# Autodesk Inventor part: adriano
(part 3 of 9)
sketch "スケッチ93"
  geometry: L1 (3.5, 3.5)-(0.5, 3.5) reference; L2 (0.5, 3.5)-(0.5, 0.5) reference; L3 (0.5, 0.5)-(3.5, 0.5) reference; L4 (3.5, 0.5)-(3.5, 3.5) reference; L5 (1.5, 2.5)-(2.5, 2.5); L6 (2.5, 2.5)-(2.5, 1.5); L7 (2.5, 1.5)-(1.5, 1.5); L8 (1.5, 1.5)-(1.5, 2.5); 1 further point
  constraints: 8 end point, 2 parallel, 1 horizontal, 1 perpendicular
  dimensions: "d958" = 1 distance between parallel lines of L1 L5; "d959" = 1 distance between parallel lines of L3 L7; "d960" = 1 distance between parallel lines of L2 L8; "d961" = 1 distance between parallel lines of L4 L6
extrude "押し出し90" join sketch "スケッチ93" distance "d962" = 3; taper "d963" = 0 deg
sketch "スケッチ94"
  geometry: L1 (0, 3)-(1, 3) reference; C1 r 0.8 at (0.5, 3); 1 further point
  constraints: 1 centre point, 1 midpoint
  dimensions: "d964" = 1.6 diameter of C1
extrude "押し出し91" join sketch "スケッチ94" distance "d967" = 0.8; taper "d968" = 0 deg
sketch "スケッチ95"
  geometry: L1 (20, 22)-(20, 26) reference; L2 (22, 0)-(22, 22) reference; L3 (22, 22)-(20, 22) reference; L4 (22, 20.8)-(23.6, 22); L5 (23.6, 22)-(20.4, 22); L6 (20.4, 22)-(22, 20.8); L7 (20, 22)-(24, 22) reference; L8 (24, 22)-(24, 34) reference; 1 further point
  constraints: 6 end point, 1 collinear, 1 point on line
  dimensions: "d969" = 0 distance between parallel lines of L7 L5; "d970" = 0.4 distance from line of L5.end L1; "d971" = 0.4 distance from line of L8 L4.end; "d972" = 1.2 distance from line of L5 L4.start
extrude "押し出し92" join sketch "スケッチ95" distance "d973" = 1; taper "d974" = 0 deg
sketch "スケッチ96"
  geometry: L1 (22, 0)-(22, 20.8) reference; L2 (22, 20.8)-(23.6, 22) reference; L3 (22, 20.8)-(20.4, 22); L4 (20.4, 22)-(23.6, 22); L5 (23.6, 22)-(22, 20.8); 2 further points
  constraints: 6 end point, 1 perpendicular
  dimensions: "d975" = 0.4 distance of point (20, 22) L3.end; "d976" = 0 distance between parallel lines of L2 L5
extrude "押し出し93" join sketch "スケッチ96" distance "d977" = 1; taper "d978" = 0 deg
sketch "スケッチ97"
  geometry: L1 (24, 34)-(20, 34) reference; L2 (20, 34)-(20, 22) reference; L3 (21.5, 31)-(22.5, 31); L4 (22.5, 31)-(22.5, 29.5); L5 (22.5, 29.5)-(21.5, 29.5); L6 (21.5, 29.5)-(21.5, 31); 1 further point
  constraints: 8 end point, 2 parallel, 1 horizontal, 1 perpendicular
  dimensions: "d979" = 1 distance of L3.start L3.end; "d981" = 1.5 distance of L3.end L4.end; "d982" = 1.5 distance between parallel lines of L6 L2; "d983" = 3 distance between parallel lines of L1 L3
extrude "押し出し94" cut sketch "スケッチ97" distance "d984" = 2; taper "d985" = 0 deg
sketch "スケッチ98"
  geometry: L1 (-19.412, -18.314)-(-19.412, 9.686) reference; L2 (7.588, -18.314)-(-19.412, -18.314) reference; L3 (-16.412, -4.314)-(-2.412, -4.314); L4 (-2.412, -4.314)-(-2.412, -14.314); L5 (-2.412, -14.314)-(-16.412, -14.314); L6 (-16.412, -14.314)-(-16.412, -4.314); 1 further point
  constraints: 8 end point, 2 parallel, 1 horizontal, 1 perpendicular
  dimensions: "d986" = 3 distance between parallel lines of L6 L1; "d987" = 4 distance between parallel lines of L2 L5; "d988" = 14 distance of L4.end L5.end; "d989" = 10 distance of L5.end L3.start
extrude "押し出し95" cut sketch "スケッチ98" distance "d990" = 0.5; taper "d991" = 0 deg
sketch "スケッチ99"
  geometry: L1 (-16.412, -4.314)-(-2.412, -4.314) reference; L2 (-16.412, -14.314)-(-16.412, -4.314) reference; L3 (-2.412, -14.314)-(-16.412, -14.314) reference; L4 (-2.412, -4.314)-(-2.412, -14.314) reference; L5 (-15.412, -5.314)-(-3.412, -5.314); L6 (-3.412, -5.314)-(-3.412, -13.314); L7 (-3.412, -13.314)-(-15.412, -13.314); L8 (-15.412, -13.314)-(-15.412, -5.314); 1 further point
  constraints: 8 end point, 2 parallel, 1 horizontal, 1 perpendicular
  dimensions: "d992" = 1 distance between parallel lines of L1 L5; "d993" = 1 distance between parallel lines of L2 L8; "d994" = 1 distance between parallel lines of L4 L6; "d995" = 1 distance between parallel lines of L3 L7
extrude "押し出し96" cut sketch "スケッチ99" distance "d996" = 1; taper "d997" = 0 deg
sketch "スケッチ100"
  geometry: L1 (-15.412, -5.314)-(-3.412, -5.314) reference; L2 (-15.412, -13.314)-(-15.412, -5.314) reference; L3 (-9.912, -8.814)-(-8.912, -8.814); L4 (-8.912, -8.814)-(-8.912, -9.814); L5 (-8.912, -9.814)-(-9.912, -9.814); L6 (-9.912, -9.814)-(-9.912, -8.814); 1 further point
  constraints: 8 end point, 2 parallel, 1 horizontal, 1 perpendicular
  dimensions: "d998" = 1 distance of L3.start L3.end; "d1000" = 1 distance of L3.end L4.end; "d1001" = 3.5 distance between parallel lines of L1 L3; "d1002" = 5.5 distance between parallel lines of L2 L6
extrude "押し出し97" join sketch "スケッチ100" distance "d1003" = 1; taper "d1004" = 0 deg
sketch "スケッチ101"
  geometry: L1 (0, 4)-(4, 4) reference; L2 (0, 0)-(0, 4) reference; L3 (0, 0)-(4, 0) reference; L4 (4, 4)-(4, 0) reference; L5 (-0.5, 4.5)-(4.5, 4.5); L6 (4.5, 4.5)-(4.5, -0.5); L7 (4.5, -0.5)-(-0.5, -0.5); L8 (-0.5, -0.5)-(-0.5, 4.5); 1 further point
  constraints: 8 end point, 2 parallel, 1 horizontal, 1 perpendicular
  dimensions: "d1005" = 0.5 distance between parallel lines of L8 L2; "d1006" = 0.5 distance between parallel lines of L5 L1; "d1007" = 0.5 distance between parallel lines of L7 L3; "d1008" = 0.5 distance between parallel lines of L6 L4
extrude "押し出し98" join sketch "スケッチ101" distance "d1009" = 1; taper "d1010" = 0 deg
sketch "スケッチ102"
  geometry: L1 (82.588, 32.686)-(82.588, 25.686) reference; L2 (113.588, 30.686)-(113.588, 11.686) reference; L3 (83.588, 25.686)-(83.588, -26.314); L4 (83.588, -26.314)-(58.588, -26.314); L5 (58.588, -26.314)-(58.588, -13.314); L6 (58.588, -13.314)-(27.588, -13.314); L7 (27.588, -13.314)-(27.588, 12.686); L8 (27.588, 12.686)-(58.588, 12.686); L9 (58.588, 12.686)-(58.588, 25.686); L10 (58.588, 25.686)-(83.588, 25.686); L11 (58.588, 25.686)-(58.588, 43.005) reference; 1 further point
  constraints: 16 end point, 6 parallel, 2 perpendicular
  dimensions: "d1012" = 52 distance of L3.start L3.end; "d1015" = 0 distance between parallel lines of L5 L9; "d1017" = 56 distance between parallel lines of L3 L7; "d1018" = 13 distance between parallel lines of L8 L10; "d1019" = 13 distance between parallel lines of L4 L6; "d1020" = 0 distance from line of L1.end L10; "d1021" = 1 distance between parallel lines of L3 L1; "d1024" = 0 distance between parallel lines of L9 L11
extrude "hotel" join sketch "スケッチ102" distance "d1022" = 34; taper "d1023" = 0 deg
sketch "スケッチ103"
  geometry: L1 (83.588, -26.314)-(83.588, 25.686) reference; L2 (83.588, 25.686)-(58.588, 25.686) reference; L3 (58.588, 25.686)-(58.588, 12.686) reference; L4 (58.588, 12.686)-(27.588, 12.686) reference; L5 (27.588, 12.686)-(27.588, -13.314) reference; L6 (27.588, -13.314)-(58.588, -13.314) reference; L7 (58.588, -13.314)-(58.588, -26.314) reference; L8 (58.588, -26.314)-(83.588, -26.314) reference; L9 (29.588, 10.686)-(29.588, -11.314); L10 (29.588, -11.314)-(60.588, -11.314); L11 (60.588, -11.314)-(60.588, -24.314); L12 (60.588, -24.314)-(81.588, -24.314); L13 (81.588, -24.314)-(81.588, 23.686); L14 (81.588, 23.686)-(60.588, 23.686); L15 (60.588, 23.686)-(60.588, 10.686); L16 (60.588, 10.686)-(29.588, 10.686); 1 further point
  constraints: 16 end point, 4 parallel, 4 perpendicular
  dimensions: "d1025" = 2 distance between parallel lines of L9 L5; "d1026" = 2 distance between parallel lines of L6 L10; "d1027" = 2 distance between parallel lines of L11 L7; "d1028" = 2 distance between parallel lines of L8 L12; "d1029" = 2 distance between parallel lines of L1 L13; "d1030" = 2 distance between parallel lines of L2 L14; "d1031" = 2 distance between parallel lines of L15 L3; "d1032" = 2 distance between parallel lines of L16 L4
extrude "押し出し100" cut sketch "スケッチ103" distance "d1033" = 34; taper "d1034" = 0 deg
sketch "スケッチ107"
  geometry: L1 (0, 0)-(0, -34) reference; L2 (0, -34)-(21, -34) reference; L3 (21, 0)-(21, -34) reference; L4 (10.5, -22)-(10.5, -34); L5 (10.5, -34)-(14.5, -34); L6 (14.5, -34)-(14.5, -22); A1 r 2 centre (12.5, -22) between (14.5, -22) and (10.5, -22); 1 further point
  constraints: 6 end point, 2 parallel, 2 point on circle, 1 centre point, 1 perpendicular
  dimensions: "d1035" = 0 distance between parallel lines of L2 L5; "d1036" = 12 distance from line of L2 A1.centre; "d1037" = 12.5 distance from line of A1.centre L1; "d1038" = 4 distance between parallel lines of L6 L4; "d1039" = 0 vertical distance of L6.end L4.start; "d1041" = 0 vertical distance of L6.end A1.centre
extrude "押し出し101" cut sketch "スケッチ107" distance "d1042" = 4; taper "d1043" = 0 deg
sketch "スケッチ108"
  geometry: L1 (52, 16)-(52, 34) reference; L2 (0, 34)-(52, 34) reference; L3 (0, 0)-(0, 34) reference; L4 (52, 0)-(0, 0) reference; L5 (0, 32.4)-(18, 32.4); L6 (18, 32.4)-(18, 16.536); L7 (18, 16.536)-(0, 16.536); L8 (0, 16.536)-(0, 32.4); L9 (34, 32.4)-(52, 32.4); L10 (52, 32.4)-(52, 16.536); L11 (52, 16.536)-(34, 16.536); L12 (34, 16.536)-(34, 32.4); L13 (52, 14.936)-(34, 14.936); L14 (34, 14.936)-(34, 0); L15 (34, 0)-(52, 0); L16 (52, 0)-(52, 14.936); L17 (18, 14.936)-(0, 14.936); L18 (0, 14.936)-(0, 0); L19 (0, 0)-(18, 0); L20 (18, 0)-(18, 14.936); 1 further point
  constraints: 32 end point, 8 parallel, 4 horizontal, 4 perpendicular, 3 point on line
  dimensions: "d1044" = 1.6 distance between parallel lines of L13 L11; "d1046" = 1.6 distance between parallel lines of L9 L2; "d1047" = 0 distance between parallel lines of L9 L5; "d1048" = 0 distance between parallel lines of L11 L7; "d1049" = 16 distance between parallel lines of L12 L6; "d1050" = 0 distance between parallel lines of L14 L12; "d1051" = 18 distance between parallel lines of L6 L3; "d1052" = 0 distance between parallel lines of L20 L6
extrude "押し出し102" cut sketch "スケッチ108" distance "d1053" = 0.5; taper "d1054" = 0 deg
sketch "スケッチ109"
  geometry: L1 (25, 0)-(25, 18) reference; L2 (0.5, 16.4)-(25, 16.4); L3 (25, 16.4)-(25, 0.536); L4 (25, 0.536)-(0.5, 0.536); L5 (0.5, 0.536)-(0.5, 16.4); L6 (0.5, 0.536)-(0, 0.536) reference; 1 further point
  constraints: 8 end point, 2 parallel, 1 horizontal, 1 perpendicular, 1 point on line
  dimensions: "d3989" = 0 distance between parallel lines of L4 L6
extrude "押し出し103" cut sketch "スケッチ109" distance "d1055" = 0.5; taper "d1056" = 0 deg
sketch "スケッチ110"
  geometry: L1 (0, 0)-(0, 34) reference; L2 (-12.5, 32.4)-(0, 32.4); L3 (0, 32.4)-(0, 16.536); L4 (0, 16.536)-(-12.5, 16.536); L5 (-12.5, 16.536)-(-12.5, 32.4); L6 (-13, 14.936)-(0, 14.936); L7 (0, 14.936)-(0, 0); L8 (0, 0)-(-13, 0); L9 (-13, 0)-(-13, 14.936); L10 (-12.5, 16.536)-(-13, 16.536) reference; 1 further point
  constraints: 16 end point, 4 parallel, 2 horizontal, 2 perpendicular, 1 point on line
  dimensions: "d3991" = 0 distance between parallel lines of L4 L10
extrude "押し出し104" cut sketch "スケッチ110" distance "d1057" = 0.5; taper "d1058" = 0 deg
sketch "スケッチ111"
  geometry: L1 (31, -34)-(31, 0) reference; L2 (-0.5, -1.6)-(31, -1.6); L3 (31, -1.6)-(31, -17.464); L4 (31, -17.464)-(-0.5, -17.464); L5 (-0.5, -17.464)-(-0.5, -1.6); L6 (31, -34)-(-0.5, -34); L7 (-0.5, -34)-(-0.5, -19.064); L8 (-0.5, -19.064)-(31, -19.064); L9 (31, -19.064)-(31, -34); L10 (0, -17.464)-(-0.5, -17.464) reference; 1 further point
  constraints: 16 end point, 4 parallel, 2 horizontal, 2 perpendicular, 1 point on line
  dimensions: "d3992" = 0 distance between parallel lines of L4 L10
extrude "押し出し105" cut sketch "スケッチ111" distance "d1059" = 0.5; taper "d1060" = 0 deg
sketch "スケッチ112"
  geometry: L1 (0, 0)-(0, 34) reference; L2 (-25.5, 32.4)-(0, 32.4); L3 (0, 32.4)-(0, 16.536); L4 (0, 16.536)-(-25.5, 16.536); L5 (-25.5, 16.536)-(-25.5, 32.4); L6 (-25.5, 14.936)-(0, 14.936); L7 (0, 14.936)-(0, 0); L8 (0, 0)-(-25.5, 0); L9 (-25.5, 0)-(-25.5, 14.936); L10 (-25.5, 16.536)-(-26, 16.536) reference; 1 further point
  constraints: 16 end point, 4 parallel, 2 horizontal, 2 perpendicular, 1 point on line
  dimensions: "d3993" = 0 distance between parallel lines of L4 L10
extrude "押し出し106" cut sketch "スケッチ112" distance "d1061" = 0.5; taper "d1062" = 0 deg
sketch "スケッチ113"
  geometry: L1 (0.5, -19.064)-(0.5, -34) reference; L2 (31, -34)-(0.5, -34) reference; L3 (31, -34)-(31, 0) reference; L4 (0.5, -1.6)-(31, -1.6); L5 (31, -1.6)-(31, -17.464); L6 (31, -17.464)-(0.5, -17.464); L7 (0.5, -17.464)-(0.5, -1.6); L8 (31, -34)-(0.5, -34); L9 (0.5, -34)-(0.5, -19.064); L10 (0.5, -19.064)-(31, -19.064); L11 (31, -19.064)-(31, -34); L12 (0.5, -17.464)-(0, -17.464) reference; 1 further point
  constraints: 16 end point, 4 parallel, 2 horizontal, 2 perpendicular, 1 point on line
  dimensions: "d3994" = 0 distance between parallel lines of L6 L12
extrude "押し出し107" cut sketch "スケッチ113" distance "d1063" = 0.5; taper "d1064" = 0 deg
sketch "スケッチ114"
  geometry: L1 (0, 0)-(0, 34) reference; L2 (-13.5, 32.4)-(0, 32.4); L3 (0, 32.4)-(0, 16.536); L4 (0, 16.536)-(-13.5, 16.536); L5 (-13.5, 16.536)-(-13.5, 32.4); L6 (-13.5, 14.936)-(0, 14.936); L7 (0, 14.936)-(0, 0); L8 (0, 0)-(-13.5, 0); L9 (-13.5, 0)-(-13.5, 14.936); L10 (-13, 16.536)-(-13.5, 16.536) reference; 1 further point
  constraints: 16 end point, 4 parallel, 2 horizontal, 2 perpendicular, 1 point on line
  dimensions: "d3995" = 0 distance between parallel lines of L4 L10
extrude "押し出し108" cut sketch "スケッチ114" distance "d1065" = 0.5; taper "d1066" = 0 deg
sketch "スケッチ115"
  geometry: L1 (0.5, -1.6)-(24.5, -1.6); L2 (24.5, -1.6)-(24.5, -17.464); L3 (24.5, -17.464)-(0.5, -17.464); L4 (0.5, -17.464)-(0.5, -1.6); L5 (0.5, -19.064)-(24.5, -19.064); L6 (24.5, -19.064)-(24.5, -34); L7 (24.5, -34)-(0.5, -34); L8 (0.5, -34)-(0.5, -19.064); 1 further point
  constraints: 16 end point, 4 parallel, 2 horizontal, 2 perpendicular
extrude "押し出し109" cut sketch "スケッチ115" distance "d1067" = 0.5; taper "d1068" = 0 deg
sketch "スケッチ116"
  geometry: L1 (34, 14.936)-(52, 14.936) reference; L2 (45, 27.4)-(46, 27.4); L3 (46, 27.4)-(46, 26.2); L4 (46, 26.2)-(45, 26.2); L5 (45, 26.2)-(45, 27.4); L6 (46.5, 27.4)-(47.5, 27.4); L7 (47.5, 27.4)-(47.5, 26.2); L8 (47.5, 26.2)-(46.5, 26.2); L9 (46.5, 26.2)-(46.5, 27.4); L10 (45, 25.7)-(46, 25.7); L11 (46, 25.7)-(46, 24.5); L12 (46, 24.5)-(45, 24.5); L13 (45, 24.5)-(45, 25.7); L14 (46.5, 25.7)-(47.5, 25.7); L15 (47.5, 25.7)-(47.5, 24.5); L16 (47.5, 24.5)-(46.5, 24.5); L17 (46.5, 24.5)-(46.5, 25.7); L18 (45, 24)-(46, 24); L19 (46, 24)-(46, 22.8); L20 (46, 22.8)-(45, 22.8); L21 (45, 22.8)-(45, 24); L22 (46.5, 24)-(47.5, 24); L23 (47.5, 24)-(47.5, 22.8); L24 (47.5, 22.8)-(46.5, 22.8); L25 (46.5, 22.8)-(46.5, 24); L26 (45, 22.3)-(46, 22.3); L27 (46, 22.3)-(46, 21.1); L28 (46, 21.1)-(45, 21.1); L29 (45, 21.1)-(45, 22.3); L30 (46.5, 22.3)-(47.5, 22.3); L31 (47.5, 22.3)-(47.5, 21.1); L32 (47.5, 21.1)-(46.5, 21.1); L33 (46.5, 21.1)-(46.5, 22.3); L34 (45, 9.936)-(46, 9.936); L35 (46, 9.936)-(46, 8.736); L36 (46, 8.736)-(45, 8.736); L37 (45, 8.736)-(45, 9.936); L38 (46.5, 9.936)-(47.5, 9.936); L39 (47.5, 9.936)-(47.5, 8.736); L40 (47.5, 8.736)-(46.5, 8.736); L41 (46.5, 8.736)-(46.5, 9.936); L42 (45, 8.236)-(46, 8.236); L43 (46, 8.236)-(46, 7.036); L44 (46, 7.036)-(45, 7.036); L45 (45, 7.036)-(45, 8.236); L46 (46.5, 8.236)-(47.5, 8.236); L47 (47.5, 8.236)-(47.5, 7.036); L48 (47.5, 7.036)-(46.5, 7.036); L49 (46.5, 7.036)-(46.5, 8.236); L50 (45, 6.536)-(46, 6.536); L51 (46, 6.536)-(46, 5.336); L52 (46, 5.336)-(45, 5.336); L53 (45, 5.336)-(45, 6.536); L54 (46.5, 6.536)-(47.5, 6.536); L55 (47.5, 6.536)-(47.5, 5.336); L56 (47.5, 5.336)-(46.5, 5.336); L57 (46.5, 5.336)-(46.5, 6.536); L58 (45, 4.836)-(46, 4.836); L59 (46, 4.836)-(46, 3.636); L60 (46, 3.636)-(45, 3.636); L61 (45, 3.636)-(45, 4.836); L62 (46.5, 4.836)-(47.5, 4.836); L63 (47.5, 4.836)-(47.5, 3.636); L64 (47.5, 3.636)-(46.5, 3.636)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; A1 r 1 centre (46, 10.436) between (46, 11.436) and (45, 10.436); A2 r 1.014 centre (46.5, 10.436) between (47.514, 10.436) and (46.5, 11.45); A3 r 1 centre (5.5, 10.436) between (5.5, 11.436) and (4.5, 10.436); A4 r 1 centre (6, 10.436) between (7, 10.436) and (6, 11.436); 1 further point
  constraints: 272 end point, 67 parallel, 36 perpendicular, 32 horizontal, 8 point on circle, 4 centre point, 1 collinear
  dimensions: "d1071" = 0.5 distance between parallel lines of L9 L3; "d1072" = 0 distance between parallel lines of L17 L9; "d1073" = 0 distance between parallel lines of L25 L17; "d1074" = 0 distance between parallel lines of L33 L25; "d1075" = 0 distance between parallel lines of L33 L41; "d1076" = 0 distance between parallel lines of L49 L41; "d1077" = 0 distance between parallel lines of L57 L49; "d1078" = 0 distance between parallel lines of L65 L57; "d1079" = 0.5 distance between parallel lines of L78 L72; "d1080" = 0.5 distance between parallel lines of L86 L80; "d1081" = 0.5 distance between parallel lines of L94 L88; "d1082" = 0.5 distance between parallel lines of L110 L104; "d1083" = 0.5 distance between parallel lines of L118 L112; "d1084" = 0.5 distance between parallel lines of L126 L120; "d1085" = 0 distance between parallel lines of L102 L98; "d1086" = 0 distance between parallel lines of L106 L110; "d1087" = 0 distance between parallel lines of L122 L126; "d1088" = 0 distance between parallel lines of L118 L114; "d1089" = 0 distance between parallel lines of L120 L116; "d1090" = 0 distance between parallel lines of L112 L108; "d1091" = 0 distance between parallel lines of L104 L100; "d1092" = 0 distance between parallel lines of L92 L96; "d1093" = 1 distance of L91.end L92.end; "d1094" = 1 distance of L95.end L96.end; "d1095" = 0 distance between parallel lines of L87 L95; "d1096" = 0 distance between parallel lines of L87 L79; "d1097" = 0 distance between parallel lines of L79 L71; "d1098" = 0 distance between parallel lines of L103 L95; "d1099" = 0 distance between parallel lines of L111 L103; "d1100" = 0 distance between parallel lines of L119 L111; "d1101" = 0 distance between parallel lines of L127 L119; "d1102" = 1 distance of L2.start L2.end; "d1103" = 1 distance of L6.start L6.end; "d1104" = 0 distance between parallel lines of L4 L72; "d1105" = 0 distance between parallel lines of L10 L78; "d1106" = 0 distance between parallel lines of L14 L10; "d1107" = 0 distance between parallel lines of L16 L12; "d1108" = 0 distance between parallel lines of L15 L7; "d1109" = 0 distance between parallel lines of L18 L86; "d1110" = 0 distance between parallel lines of L18 L22; "d1111" = 0 distance between parallel lines of L24 L20; "d1112" = 0 distance between parallel lines of L26 L94; "d1113" = 0 distance between parallel lines of L30 L26; "d1114" = 0 distance between parallel lines of L20 L88; "d1115" = 0 distance between parallel lines of L32 L28; "d1116" = 0 distance between parallel lines of L34 L102; "d1117" = 0 distance between parallel lines of L38 L34; "d1118" = 0 distance between parallel lines of L40 L36; "d1119" = 0 distance between parallel lines of L42 L110; "d1120" = 0 distance between parallel lines of L46 L42; "d1121" = 0 distance between parallel lines of L44 L48; "d1122" = 0 distance between parallel lines of L118 L50; "d1123" = 0 distance between parallel lines of L50 L54; "d1124" = 0 distance between parallel lines of L52 L56; "d1127" = 0 distance between parallel lines of L67 L77; "d1128" = 0 distance between parallel lines of L75 L69; "d1129" = 0.5 distance between parallel lines of L69 L73; "d1130" = 4 distance between parallel lines of L130 L67; "d1131" = 1 distance of L70.start L70.end; "d1132" = 0 distance between parallel lines of L77 L85; "d1133" = 0 distance between parallel lines of L93 L85; "d1134" = 1 distance of L66.start L66.end; "d1135" = 1.2 distance of L66.end L67.end; "d1136" = 1.2 distance of L76.end L74.start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
extrude "window00" cut sketch "スケッチ116" distance "d1201" = 30; taper "d1202" = 0 deg
sketch "スケッチ117"
  geometry: L1 (40.5, 9.936)-(39.5, 9.936); L2 (39.5, 9.936)-(39.5, 8.736); L3 (39.5, 8.736)-(40.5, 8.736); L4 (40.5, 8.736)-(40.5, 9.936); L5 (40.5, 8.236)-(39.5, 8.236); L6 (39.5, 8.236)-(39.5, 7.036); L7 (39.5, 7.036)-(40.5, 7.036); L8 (40.5, 7.036)-(40.5, 8.236); L9 (40.5, 6.536)-(39.5, 6.536); L10 (39.5, 6.536)-(39.5, 5.336); L11 (39.5, 5.336)-(40.5, 5.336); L12 (40.5, 5.336)-(40.5, 6.536); L13 (40.5, 4.836)-(39.5, 4.836); L14 (39.5, 4.836)-(39.5, 3.636); L15 (39.5, 3.636)-(40.5, 3.636); L16 (40.5, 3.636)-(40.5, 4.836); L17 (39, 3.636)-(38, 3.636); L18 (38, 3.636)-(38, 4.836); L19 (38, 4.836)-(39, 4.836); L20 (39, 4.836)-(39, 3.636); L21 (39, 5.336)-(38, 5.336); L22 (38, 5.336)-(38, 6.536); L23 (38, 6.536)-(39, 6.536); L24 (39, 6.536)-(39, 5.336); L25 (39, 7.036)-(38, 7.036); L26 (38, 7.036)-(38, 8.236); L27 (38, 8.236)-(39, 8.236); L28 (39, 8.236)-(39, 7.036); L29 (39, 8.736)-(38, 8.736); L30 (38, 8.736)-(38, 9.936); L31 (38, 9.936)-(39, 9.936); L32 (39, 9.936)-(39, 8.736); L33 (40.5, 21.1)-(39.5, 21.1); L34 (39.5, 21.1)-(39.5, 22.3); L35 (39.5, 22.3)-(40.5, 22.3); L36 (40.5, 22.3)-(40.5, 21.1); L37 (39, 21.1)-(38, 21.1); L38 (38, 21.1)-(38, 22.3); L39 (38, 22.3)-(39, 22.3); L40 (39, 22.3)-(39, 21.1); L41 (39, 22.8)-(38, 22.8); L42 (38, 22.8)-(38, 24); L43 (38, 24)-(39, 24); L44 (39, 24)-(39, 22.8); L45 (39.5, 24)-(40.5, 24); L46 (40.5, 24)-(40.5, 22.8); L47 (40.5, 22.8)-(39.5, 22.8); L48 (39.5, 22.8)-(39.5, 24); L49 (40.5, 24.5)-(39.5, 24.5); L50 (39.5, 24.5)-(39.5, 25.7); L51 (39.5, 25.7)-(40.5, 25.7); L52 (40.5, 25.7)-(40.5, 24.5); L53 (39, 25.7)-(38, 25.7); L54 (38, 25.7)-(38, 24.5); L55 (38, 24.5)-(39, 24.5); L56 (39, 24.5)-(39, 25.7); L57 (38, 26.2)-(39, 26.2); L58 (39, 26.2)-(39, 27.4); L59 (39, 27.4)-(38, 27.4); L60 (38, 27.4)-(38, 26.2); L61 (39.5, 27.4)-(40.5, 27.4); L62 (40.5, 27.4)-(40.5, 26.2); L63 (40.5, 26.2)-(39.5, 26.2); L64 (39.5, 26.2)-(39.5, 27.4)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; A1 r 1 centre (13, 10.436) between (14, 10.436) and (13, 11.436); A2 r 1 centre (39, 10.436) between (39, 11.436) and (38, 10.436); A3 r 1 centre (39.5, 10.436) between (40.5, 10.436) and (39.5, 11.436); A4 r 1 centre (12.5, 10.436) between (12.5, 11.436) and (11.5, 10.436); 1 further point
  constraints: 274 end point, 65 parallel, 39 perpendicular, 32 horizontal, 8 point on circle, 4 centre point
  dimensions: "d1203" = 1 distance of L122.end L123.end; "d1205" = 1 distance of L125.start L125.end; "d1206" = 0.5 distance between parallel lines of L128 L122; "d1207" = 0 distance between parallel lines of L114 L128; "d1208" = 0 distance between parallel lines of L126 L116; "d1209" = 0 distance between parallel lines of L112 L114; "d1210" = 0 distance between parallel lines of L110 L116; "d1211" = 0 distance between parallel lines of L104 L112; "d1212" = 0 distance between parallel lines of L102 L110; "d1213" = 0 distance between parallel lines of L130 L104; "d1214" = 0 distance between parallel lines of L72 L130; "d1215" = 0 distance between parallel lines of L80 L72; "d1216" = 0 distance between parallel lines of L88 L80; "d1217" = 0 distance between parallel lines of L88 L96; "d1218" = 1 distance of L58.end L59.end; "d1219" = 0.5 distance between parallel lines of L64 L58; "d1220" = 1 distance of L61.start L61.end; "d1221" = 0 distance between parallel lines of L56 L58; "d1222" = 0 distance between parallel lines of L60 L54; "d1223" = 0 distance between parallel lines of L42 L54; "d1224" = 0 distance between parallel lines of L56 L44; "d1225" = 0 distance between parallel lines of L40 L44; "d1226" = 0 distance between parallel lines of L50 L64; "d1227" = 0 distance between parallel lines of L48 L50; "d1228" = 0 distance between parallel lines of L34 L48; "d1229" = 0 distance between parallel lines of L134 L34; "d1230" = 0 distance between parallel lines of L2 L134; "d1231" = 0 distance between parallel lines of L6 L2; "d1232" = 0 distance between parallel lines of L10 L6; "d1233" = 0 distance between parallel lines of L14 L10; "d1234" = 0 distance from line of L4 L135.end; "d1235" = 0 distance between parallel lines of L8 L4; "d1236" = 0 distance between parallel lines of L12 L8; "d1237" = 0 distance between parallel lines of L16 L12; "d1238" = 0 distance between parallel lines of L4 L36; "d1239" = 0 distance between parallel lines of L36 L46; "d1240" = 0 distance between parallel lines of L46 L52; "d1241" = 0 distance between parallel lines of L52 L62; "d1242" = 0 vertical distance of L132.start L134.start; "d1243" = 0 distance between parallel lines of L135 L133; "d1244" = 0 distance from line of L30 L133.end; "d1245" = 0 distance between parallel lines of L26 L30; "d1246" = 0 distance between parallel lines of L22 L26; "d1247" = 0 distance between parallel lines of L18 L22; "d1249" = 0 distance from line of L70 L131.end; "d1250" = 0 distance between parallel lines of L78 L70; "d1251" = 0 distance between parallel lines of L86 L78; "d1252" = 0 distance between parallel lines of L94 L86; "d1253" = 1.2 distance of L123.end L121.start; "d1254" = 0.5 distance between parallel lines of L117 L121; "d1255" = 1.2 distance of L117.end L118.end; "d1256" = 0.5 distance between parallel lines of L107 L119; "d1257" = 1.2 distance of L107.end L105.start; "d1258" = 0.5 distance between parallel lines of L99 L105; "d1259" = 1.2 distance of L99.end L97.start; "d1260" = 0 distance between parallel lines of L127 L121; "d1261" = 0 distance between parallel lines of L115 L117; "d1262" = 0 distance between parallel lines of L113 L119; "d1263" = 0 distance between parallel lines of L109 L107; "d1264" = 0 distance between parallel lines of L111 L105; "d1265" = 0 distance between parallel lines of L101 L99; "d1266" = 0 distance between parallel lines of L103 L97; "d1267" = 0 distance between parallel lines of L131 L129; "d1268" = 0 distance between parallel lines of L69 L65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
extrude "押し出し111" cut sketch "スケッチ117" distance "d1337" = 4; taper "d1338" = 0 deg
sketch "スケッチ118"
  geometry: L1 (39, 8.236)-(39, 7.036) reference; L2 (39, 7.036)-(38, 7.036) reference; L3 (38, 7.036)-(38, 8.236) reference; L4 (38, 8.236)-(39, 8.236) reference; L5 (39, 4.836)-(39, 3.636) reference; L6 (39, 3.636)-(38, 3.636) reference; L7 (38, 3.636)-(38, 4.836) reference; L8 (38, 4.836)-(39, 4.836) reference; L9 (39.5, 5.336)-(39.5, 6.536) reference; L10 (39.5, 6.536)-(40.5, 6.536) reference; L11 (40.5, 6.536)-(40.5, 5.336) reference; L12 (40.5, 5.336)-(39.5, 5.336) reference; L13 (39.5, 8.736)-(39.5, 9.936) reference; L14 (39.5, 9.936)-(40.5, 9.936) reference; L15 (40.5, 9.936)-(40.5, 8.736) reference; L16 (40.5, 8.736)-(39.5, 8.736) reference; L17 (39, 11.436)-(39, 10.436) reference; L18 (39, 10.436)-(38, 10.436) reference; L19 (40.5, 10.436)-(39.5, 10.436) reference; L20 (39.5, 10.436)-(39.5, 11.436) reference; L21 (39.5, 7.036)-(39.5, 8.236) reference; L22 (39.5, 8.236)-(40.5, 8.236) reference; L23 (40.5, 8.236)-(40.5, 7.036) reference; L24 (40.5, 7.036)-(39.5, 7.036) reference; L25 (39.5, 3.636)-(39.5, 4.836) reference; L26 (39.5, 4.836)-(40.5, 4.836) reference; L27 (40.5, 4.836)-(40.5, 3.636) reference; L28 (40.5, 3.636)-(39.5, 3.636) reference; L29 (39, 6.536)-(39, 5.336) reference; L30 (39, 5.336)-(38, 5.336) reference; L31 (38, 5.336)-(38, 6.536) reference; L32 (38, 6.536)-(39, 6.536) reference; L33 (39, 9.936)-(39, 8.736) reference; L34 (39, 8.736)-(38, 8.736) reference; L35 (38, 8.736)-(38, 9.936) reference; L36 (38, 9.936)-(39, 9.936) reference; L37 (45, 3.636)-(45, 4.836) reference; L38 (45, 4.836)-(46, 4.836) reference; L39 (46, 4.836)-(46, 3.636) reference; L40 (46, 3.636)-(45, 3.636) reference; L41 (45, 5.336)-(45, 6.536) reference; L42 (45, 6.536)-(46, 6.536) reference; L43 (46, 6.536)-(46, 5.336) reference; L44 (46, 5.336)-(45, 5.336) reference; L45 (45, 7.036)-(45, 8.236) reference; L46 (45, 8.236)-(46, 8.236) reference; L47 (46, 8.236)-(46, 7.036) reference; L48 (46, 7.036)-(45, 7.036) reference; L49 (45, 8.736)-(45, 9.936) reference; L50 (45, 9.936)-(46, 9.936) reference; L51 (46, 9.936)-(46, 8.736) reference; L52 (46, 8.736)-(45, 8.736) reference; L53 (46, 11.436)-(46, 10.436) reference; L54 (46, 10.436)-(45, 10.436) reference; L55 (47.514, 10.436)-(46.5, 10.436) reference; L56 (46.5, 10.436)-(46.5, 11.45) reference; L57 (46.5, 8.736)-(46.5, 9.936) reference; L58 (46.5, 9.936)-(47.5, 9.936) reference; L59 (47.5, 9.936)-(47.5, 8.736) reference; L60 (47.5, 8.736)-(46.5, 8.736) reference; L61 (46.5, 7.036)-(46.5, 8.236) reference; L62 (46.5, 8.236)-(47.5, 8.236) reference; L63 (47.5, 8.236)-(47.5, 7.036) reference; L64 (47.5, 7.036)-(46.5, 7.036) reference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; A1 r 1 centre (39, 10.436) between (39, 11.436) and (38, 10.436) reference; A2 r 1 centre (39.5, 10.436) between (40.5, 10.436) and (39.5, 11.436) reference; A3 r 1 centre (46, 10.436) between (46, 11.436) and (45, 10.436) reference; A4 r 1.014 centre (46.5, 10.436) between (47.514, 10.436) and (46.5, 11.45) reference; A5 r 2 centre (5.75, 10.5) between (7.75, 10.5) and (3.75, 10.5); A6 r 2 centre (12.75, 10.5) between (14.75, 10.5) and (10.75, 10.5); A7 r 2 centre (39.25, 10.5) between (41.25, 10.5) and (37.25, 10.5); A8 r 2 centre (46.25, 10.436) between (48.25, 10.436) and (44.25, 10.436); 1 further point
  constraints: 56 end point, 16 parallel, 8 perpendicular, 8 point on circle, 8 tangent, 4 centre point, 4 horizontal, 2 point on line
  dimensions: "d1339" = 4 distance of L74.start L74.end; "d1341" = 4 distance of L78.start L78.end; "d1342" = 4 distance of L82.start L82.end; "d1343" = 4 distance of L86.start L86.end; "d1344" = 3 distance between parallel lines of L81 L75; "d1345" = 3 distance between parallel lines of L89 L83; "d1346" = 3.25 distance between parallel lines of L102 L77; "d1347" = 3.25 distance between parallel lines of L103 L87; "d1348" = 0 distance between parallel lines of L96 L77; "d1349" = 0 distance between parallel lines of L98 L75; "d1350" = 0 distance between parallel lines of L81 L99; "d1351" = 0 distance between parallel lines of L101 L79; "d1352" = 0 distance between parallel lines of L90 L85; "d1353" = 0 distance between parallel lines of L83 L92; "d1354" = 0 distance between parallel lines of L93 L89; "d1355" = 0 distance between parallel lines of L95 L87; "d1356" = 7.5 distance of L96.start L96.end; "d1357" = 7.5 distance of L76.end L74.start; "d1358" = 4 distance between parallel lines of L76 L104; "d1359" = 3 distance between parallel lines of L105 L97; "d1360" = 0 distance between parallel lines of L100 L97; "d1361" = 0 distance between parallel lines of L91 L100; "d1362" = 0 distance between parallel lines of L94 L91; "d1363" = 0 distance between parallel lines of L78 L74; "d1364" = 0 distance between parallel lines of L82 L78; "d1365" = 0 distance between parallel lines of L86 L82; "d1366" = 0 distance between parallel lines of L80 L76; "d1367" = 0 distance between parallel lines of L84 L80; "d1368" = 0 distance between parallel lines of L88 L84; "d1369" = 0 vertical distance of A6.centre A5.centre; "d1370" = 0 vertical distance of A7.centre A6.centre
extrude "押し出し112" cut sketch "スケッチ118" distance "d1371" = 0.5; taper "d1372" = 0 deg
sketch "スケッチ119"
  geometry: L1 (-6, 4.836)-(-6, 3.636) reference; L2 (-6, 3.636)-(-7, 3.636) reference; L3 (-7, 3.636)-(-7, 4.836) reference; L4 (-7, 4.836)-(-6, 4.836) reference; L5 (-6, 6.536)-(-6, 5.336) reference; L6 (-6, 5.336)-(-7, 5.336) reference; L7 (-7, 5.336)-(-7, 6.536) reference; L8 (-7, 6.536)-(-6, 6.536) reference; L9 (-6, 8.236)-(-6, 7.036) reference; L10 (-6, 7.036)-(-7, 7.036) reference; L11 (-7, 7.036)-(-7, 8.236) reference; L12 (-7, 8.236)-(-6, 8.236) reference; L13 (-6, 9.936)-(-6, 8.736) reference; L14 (-6, 8.736)-(-7, 8.736) reference; L15 (-7, 8.736)-(-7, 9.936) reference; L16 (-7, 9.936)-(-6, 9.936) reference; L17 (-7, 10.436)-(-7, 11.436) reference; L18 (-6, 10.436)-(-7, 10.436) reference; L19 (-7.5, 10.436)-(-8.514, 10.436) reference; L20 (-7.5, 11.45)-(-7.5, 10.436) reference; L21 (-7.5, 9.936)-(-7.5, 8.736) reference; L22 (-7.5, 8.736)-(-8.5, 8.736) reference; L23 (-8.5, 8.736)-(-8.5, 9.936) reference; L24 (-8.5, 9.936)-(-7.5, 9.936) reference; L25 (-7.5, 8.236)-(-7.5, 7.036) reference; L26 (-7.5, 7.036)-(-8.5, 7.036) reference; L27 (-8.5, 7.036)-(-8.5, 8.236) reference; L28 (-8.5, 8.236)-(-7.5, 8.236) reference; L29 (-7.5, 6.536)-(-7.5, 5.336) reference; L30 (-7.5, 5.336)-(-8.5, 5.336) reference; L31 (-8.5, 5.336)-(-8.5, 6.536) reference; L32 (-8.5, 6.536)-(-7.5, 6.536) reference; L33 (-7.5, 4.836)-(-7.5, 3.636) reference; L34 (-7.5, 3.636)-(-8.5, 3.636) reference; L35 (-8.5, 3.636)-(-8.5, 4.836) reference; L36 (-8.5, 4.836)-(-7.5, 4.836) reference; L37 (0.5, 0)-(-13, 0) reference; L38 (-9.25, 28.036)-(-5.25, 28.036); L39 (-5.25, 28.036)-(-5.25, 20.536); L40 (-5.25, 20.536)-(-9.25, 20.536); L41 (-9.25, 20.536)-(-9.25, 28.036); L42 (31.25, 27.981)-(35.25, 27.981); L43 (35.25, 27.981)-(35.25, 20.536); L44 (35.25, 20.536)-(31.25, 20.536); L45 (31.25, 20.536)-(31.25, 27.981); L46 (31.25, 10.436)-(31.25, 3); L47 (31.25, 3)-(35.25, 3); L48 (35.25, 3)-(35.25, 10.436); L49 (-9.25, 10.436)-(-9.25, 3); L50 (-9.25, 3)-(-5.25, 3); L51 (-5.25, 3)-(-5.25, 10.436); L52 (-12.5, 16.536)-(-12.5, 32.4) reference; L53 (38.5, 16.536)-(38.5, 32.4) reference; L54 (-13, 16.536)-(-12.5, 16.536) reference; L55 (0, 16.536)-(-12.5, 16.536) reference; A1 r 1 centre (-7, 10.436) between (-6, 10.436) and (-7, 11.436) reference; A2 r 1.014 centre (-7.5, 10.436) between (-7.5, 11.45) and (-8.514, 10.436) reference; A3 r 2 centre (-7.25, 10.436) between (-5.25, 10.436) and (-9.25, 10.436); A4 r 2 centre (33.25, 10.436) between (35.25, 10.436) and (31.25, 10.436); 2 further points
  constraints: 28 end point, 7 parallel, 4 perpendicular, 4 point on circle, 4 tangent, 2 centre point, 2 horizontal, 1 collinear, 1 point on line
  dimensions: "d1373" = 3.25 distance between parallel lines of L52 L41; "d1374" = 0 distance between parallel lines of L41 L49; "d1375" = 3.25 distance between parallel lines of L53 L43; "d1376" = 0 distance between parallel lines of L48 L43; "d1377" = 0 distance between parallel lines of L46 L45; "d1378" = 0 distance between parallel lines of L51 L39; "d1379" = 4 distance of L38.start L38.end; "d1380" = 4 distance of L42.start L42.end; "d1381" = 7.5 distance of L40.end L38.start; "d1382" = 0 distance between parallel lines of L44 L40; "d1384" = 3 distance between parallel lines of L37 L50; "d1385" = 0 distance between parallel lines of L47 L50; "d3990" = 4 distance between parallel lines of L55 L40
extrude "押し出し113" cut sketch "スケッチ119" distance "d1386" = 0.5; taper "d1387" = 0 deg
sketch "スケッチ121"
  geometry: L1 (0.5, -17.464)-(0.5, -1.6) reference; L2 (5.75, -7.8)-(4.75, -7.8); L3 (4.75, -7.8)-(4.75, -6.6); L4 (4.75, -6.6)-(5.75, -6.6); L5 (5.75, -6.6)-(5.75, -7.8); L6 (6.25, -6.6)-(7.25, -6.6); L7 (7.25, -6.6)-(7.25, -7.8); L8 (7.25, -7.8)-(6.25, -7.8); L9 (6.25, -7.8)-(6.25, -6.6); L10 (4.75, -8.3)-(5.75, -8.3); L11 (5.75, -8.3)-(5.75, -9.5); L12 (5.75, -9.5)-(4.75, -9.5); L13 (4.75, -9.5)-(4.75, -8.3); L14 (6.25, -8.3)-(7.25, -8.3); L15 (7.25, -8.3)-(7.25, -9.5); L16 (7.25, -9.5)-(6.25, -9.5); L17 (6.25, -9.5)-(6.25, -8.3); L18 (4.75, -10)-(5.75, -10); L19 (5.75, -10)-(5.75, -11.2); L20 (5.75, -11.2)-(4.75, -11.2); L21 (4.75, -11.2)-(4.75, -10); L22 (6.25, -10)-(7.25, -10); L23 (7.25, -10)-(7.25, -11.2); L24 (7.25, -11.2)-(6.25, -11.2); L25 (6.25, -11.2)-(6.25, -10); L26 (4.75, -11.7)-(5.75, -11.7); L27 (5.75, -11.7)-(5.75, -12.9); L28 (5.75, -12.9)-(4.75, -12.9); L29 (4.75, -12.9)-(4.75, -11.7); L30 (6.25, -11.7)-(7.25, -11.7); L31 (7.25, -11.7)-(7.25, -12.9); L32 (7.25, -12.9)-(6.25, -12.9); L33 (6.25, -12.9)-(6.25, -11.7); L34 (11.25, -6.6)-(12.25, -6.6); L35 (12.25, -6.6)-(12.25, -7.8); L36 (12.25, -7.8)-(11.25, -7.8); L37 (11.25, -7.8)-(11.25, -6.6); L38 (12.75, -6.6)-(13.75, -6.6); L39 (13.75, -6.6)-(13.75, -7.8); L40 (13.75, -7.8)-(12.75, -7.8); L41 (12.75, -7.8)-(12.75, -6.6); L42 (11.283, -8.3)-(12.25, -8.3); L43 (12.25, -8.3)-(12.25, -9.5); L44 (12.25, -9.5)-(11.283, -9.5); L45 (11.283, -9.5)-(11.283, -8.3); L46 (12.75, -8.3)-(13.75, -8.3); L47 (13.75, -8.3)-(13.75, -9.5); L48 (13.75, -9.5)-(12.75, -9.5); L49 (12.75, -9.5)-(12.75, -8.3); L50 (11.283, -10)-(12.25, -10); L51 (12.25, -10)-(12.25, -11.2); L52 (12.25, -11.2)-(11.283, -11.2); L53 (11.283, -11.2)-(11.283, -10); L54 (12.75, -10)-(13.75, -10); L55 (13.75, -10)-(13.75, -11.2); L56 (13.75, -11.2)-(12.75, -11.2); L57 (12.75, -11.2)-(12.75, -10); L58 (11.25, -11.7)-(12.25, -11.7); L59 (12.25, -11.7)-(12.25, -12.9); L60 (12.25, -12.9)-(11.25, -12.9); L61 (11.25, -12.9)-(11.25, -11.7); L62 (12.75, -11.7)-(13.75, -11.7); L63 (13.75, -11.7)-(13.75, -12.9); L64 (13.75, -12.9)-(12.75, -12.9)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; A1 r 1 centre (5.75, -23.564) between (5.75, -22.564) and (4.75, -23.564); A2 r 1 centre (6.25, -23.564) between (7.25, -23.564) and (6.25, -22.564); A3 r 1 centre (12.25, -23.564) between (12.25, -22.564) and (11.25, -23.564); A4 r 1 centre (12.75, -23.564) between (13.75, -23.564) and (12.75, -22.564); A5 r 1 centre (18.75, -23.564) between (18.75, -22.564) and (17.75, -23.564); A6 r 1 centre (19.25, -23.564) between (20.25, -23.564) and (19.25, -22.564); 1 further point
  constraints: 408 end point, 101 equal length, 55 perpendicular, 48 horizontal, 12 point on circle, 6 centre point
  dimensions: "d1388" = 0.5 distance between parallel lines of L9 L5; "d1390" = 0.5 distance between parallel lines of L41 L35; "d1391" = 0.5 distance between parallel lines of L73 L67; "d1392" = 1 distance of L3.end L4.end; "d1393" = 1 distance of L6.start L6.end; "d1394" = 1 distance of L34.start L34.end; "d1395" = 1 distance of L38.start L38.end; "d1396" = 1 distance of L66.start L66.end; "d1397" = 1 distance of L70.start L70.end; "d1398" = 4.25 distance between parallel lines of L3 L1; "d1399" = 4 distance between parallel lines of L37 L7; "d1400" = 4 distance between parallel lines of L69 L39; "d1401" = 0 distance between parallel lines of L71 L79; "d1402" = 0 distance between parallel lines of L79 L87; "d1403" = 0 distance between parallel lines of L87 L95; "d1404" = 0 distance between parallel lines of L75 L67; "d1405" = 0 distance between parallel lines of L75 L83; "d1406" = 0 distance between parallel lines of L83 L91; "d1407" = 0 distance between parallel lines of L39 L47; "d1408" = 0 distance between parallel lines of L47 L55; "d1409" = 0 distance between parallel lines of L55 L63; "d1410" = 0 distance between parallel lines of L43 L35; "d1411" = 0 distance between parallel lines of L43 L51; "d1412" = 0 distance between parallel lines of L51 L59; "d1413" = 0 distance between parallel lines of L15 L7; "d1414" = 0 distance between parallel lines of L23 L15; "d1415" = 0 distance between parallel lines of L23 L31; "d1416" = 0 distance between parallel lines of L11 L5; "d1417" = 0 distance between parallel lines of L11 L19; "d1418" = 0 distance between parallel lines of L19 L27; "d1419" = 0 distance from line of L197.end L95; "d1420" = 0 distance from line of L197.end L111; "d1421" = 0 distance between parallel lines of L111 L167; "d1422" = 0 distance between parallel lines of L167 L175; "d1423" = 0 distance between parallel lines of L167 L183; "d1424" = 0 distance between parallel lines of L195 L91; "d1425" = 0 distance between parallel lines of L195 L107; "d1426" = 0 distance between parallel lines of L107 L163; "d1427" = 0 distance between parallel lines of L163 L171; "d1428" = 0 distance between parallel lines of L171 L179; "d1429" = 0 distance from line of L193.end L63; "d1430" = 0 distance from line of L193.end L103; "d1431" = 0 distance between parallel lines of L103 L151; "d1432" = 0 distance between parallel lines of L151 L155; "d1433" = 0 distance between parallel lines of L155 L159; "d1434" = 0 distance between parallel lines of L191 L59; "d1436" = 0 distance between parallel lines of L99 L191; "d1437" = 0 distance between parallel lines of L139 L99; "d1438" = 0 distance between parallel lines of L143 L139; "d1439" = 0 distance between parallel lines of L147 L139; "d1443" = 0 distance between parallel lines of L127 L119; "d1444" = 0 distance between parallel lines of L135 L127; "d1445" = 0 distance between parallel lines of L187 L27; "d1448" = 0 distance between parallel lines of L123 L115; "d1449" = 0 distance between parallel lines of L131 L123; "d1450" = 0 vertical distance of L192.start L191.end; "d1451" = 0 vertical distance of L196.start L195.end; "d1453" = 0 distance between parallel lines of L132 L136; "d1454" = 0 distance between parallel lines of L136 L148; "d1455" = 0 distance between parallel lines of L148 L160; "d1456" = 0 distance between parallel lines of L160 L180; "d1457" = 0 distance between parallel lines of L180 L184; "d1458" = 1.2 distance of L132.end L130.start; "d1459" = 0.5 distance between parallel lines of L130 L124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
extrude "押し出し114" cut sketch "スケッチ121" distance "d1615" = 52; taper "d1616" = 0 deg
sketch "スケッチ122"
  geometry: L1 (4.75, -25.264)-(4.75, -24.064) reference; L2 (4.75, -24.064)-(5.75, -24.064) reference; L3 (5.75, -24.064)-(5.75, -25.264) reference; L4 (5.75, -25.264)-(4.75, -25.264) reference; L5 (17.75, -25.264)-(17.75, -24.064) reference; L6 (17.75, -24.064)-(18.75, -24.064) reference; L7 (18.75, -24.064)-(18.75, -25.264) reference; L8 (18.75, -25.264)-(17.75, -25.264) reference; L9 (12.75, -25.264)-(12.75, -24.064) reference; L10 (12.75, -24.064)-(13.75, -24.064) reference; L11 (13.75, -24.064)-(13.75, -25.264) reference; L12 (13.75, -25.264)-(12.75, -25.264) reference; L13 (17.75, -30.364)-(17.75, -29.164) reference; L14 (17.75, -29.164)-(18.75, -29.164) reference; L15 (18.75, -29.164)-(18.75, -30.364) reference; L16 (18.75, -30.364)-(17.75, -30.364) reference; L17 (17.75, -28.664)-(17.75, -27.464) reference; L18 (17.75, -27.464)-(18.75, -27.464) reference; L19 (18.75, -27.464)-(18.75, -28.664) reference; L20 (18.75, -28.664)-(17.75, -28.664) reference; L21 (17.75, -26.964)-(17.75, -25.764) reference; L22 (17.75, -25.764)-(18.75, -25.764) reference; L23 (18.75, -25.764)-(18.75, -26.964) reference; L24 (18.75, -26.964)-(17.75, -26.964) reference; L25 (12.75, -28.664)-(12.75, -27.464) reference; L26 (12.75, -27.464)-(13.75, -27.464) reference; L27 (13.75, -27.464)-(13.75, -28.664) reference; L28 (13.75, -28.664)-(12.75, -28.664) reference; L29 (11.25, -30.364)-(11.25, -29.164) reference; L30 (11.25, -29.164)-(12.25, -29.164) reference; L31 (12.25, -29.164)-(12.25, -30.364) reference; L32 (12.25, -30.364)-(11.25, -30.364) reference; L33 (11.25, -26.964)-(11.25, -25.764) reference; L34 (11.25, -25.764)-(12.25, -25.764) reference; L35 (12.25, -25.764)-(12.25, -26.964) reference; L36 (12.25, -26.964)-(11.25, -26.964) reference; L37 (6.25, -30.364)-(6.25, -29.164) reference; L38 (6.25, -29.164)-(7.25, -29.164) reference; L39 (7.25, -29.164)-(7.25, -30.364) reference; L40 (7.25, -30.364)-(6.25, -30.364) reference; L41 (6.25, -28.664)-(6.25, -27.464) reference; L42 (6.25, -27.464)-(7.25, -27.464) reference; L43 (7.25, -27.464)-(7.25, -28.664) reference; L44 (7.25, -28.664)-(6.25, -28.664) reference; L45 (6.25, -26.964)-(6.25, -25.764) reference; L46 (6.25, -25.764)-(7.25, -25.764) reference; L47 (7.25, -25.764)-(7.25, -26.964) reference; L48 (7.25, -26.964)-(6.25, -26.964) reference; L49 (18.75, -22.564)-(18.75, -23.564) reference; L50 (18.75, -23.564)-(17.75, -23.564) reference; L51 (12.25, -22.564)-(12.25, -23.564) reference; L52 (12.25, -23.564)-(11.25, -23.564) reference; L53 (5.75, -22.564)-(5.75, -23.564) reference; L54 (5.75, -23.564)-(4.75, -23.564) reference; L55 (7.25, -23.564)-(6.25, -23.564) reference; L56 (6.25, -23.564)-(6.25, -22.564) reference; L57 (13.75, -23.564)-(12.75, -23.564) reference; L58 (12.75, -23.564)-(12.75, -22.564) reference; L59 (20.25, -23.564)-(19.25, -23.564) reference; L60 (19.25, -23.564)-(19.25, -22.564) reference; L61 (4.75, -26.964)-(4.75, -25.764) reference; L62 (4.75, -25.764)-(5.75, -25.764) reference; L63 (5.75, -25.764)-(5.75, -26.964) reference; L64 (5.75, -26.964)-(4.75, -26.964) reference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; A1 r 1 centre (18.75, -23.564) between (18.75, -22.564) and (17.75, -23.564) reference; A2 r 1 centre (12.25, -23.564) between (12.25, -22.564) and (11.25, -23.564) reference; A3 r 1 centre (5.75, -23.564) between (5.75, -22.564) and (4.75, -23.564) reference; A4 r 1 centre (6.25, -23.564) between (7.25, -23.564) and (6.25, -22.564) reference; A5 r 1 centre (12.75, -23.564) between (13.75, -23.564) and (12.75, -22.564) reference; A6 r 1 centre (19.25, -23.564) between (20.25, -23.564) and (19.25, -22.564) reference; A7 r 2 centre (6, -23.564) between (8, -23.564) and (4, -23.564); A8 r 2 centre (12.5, -23.564) between (14.5, -23.564) and (10.5, -23.564); A9 r 2 centre (19, -23.564) between (21, -23.564) and (17, -23.564); 1 further point
  constraints: 42 end point, 12 parallel, 6 perpendicular, 6 point on circle, 6 tangent, 3 centre point, 3 horizontal, 1 point on line
  dimensions: "d1618" = 4 distance of L110.start L110.end; "d1620" = 4 distance of L114.start L114.end; "d1621" = 4 distance of L118.start L118.end; "d1622" = 2.5 distance between parallel lines of L117 L111; "d1623" = 2.5 distance between parallel lines of L121 L115; "d1624" = 3.5 distance between parallel lines of L113 L131; "d1625" = 0 distance between parallel lines of L122 L113; "d1626" = 0 distance between parallel lines of L124 L111; "d1627" = 0 distance between parallel lines of L117 L125; "d1628" = 0 distance between parallel lines of L115 L127; "d1629" = 0 distance between parallel lines of L128 L121; "d1630" = 0 distance between parallel lines of L119 L130; "d1631" = 3 distance between parallel lines of L109 L123; "d1632" = 0 distance between parallel lines of L123 L126; "d1633" = 0 distance between parallel lines of L129 L126; "d1634" = 7.5 distance of L118.end L119.end; "d1635" = 0 distance between parallel lines of L120 L116; "d1636" = 0 distance between parallel lines of L112 L116; "d1639" = 0 vertical distance of A9.centre A8.centre; "d1647" = 0 vertical distance of A8.centre A7.centre; "d2054" = 4.3 distance between parallel lines of L110 L132; "d2055" = 0 distance between parallel lines of L114 L110
extrude "押し出し115" cut sketch "スケッチ122" distance "d1640" = 0.5; taper "d1641" = 0 deg
sketch "スケッチ124"
  geometry: L1 (7.25, 6.3)-(7.25, 5.1) reference; L2 (7.25, 5.1)-(6.25, 5.1) reference; L3 (6.25, 5.1)-(6.25, 6.3) reference; L4 (6.25, 6.3)-(7.25, 6.3) reference; L5 (7.25, 8)-(7.25, 6.8) reference; L6 (7.25, 6.8)-(6.25, 6.8) reference; L7 (6.25, 6.8)-(6.25, 8) reference; L8 (6.25, 8)-(7.25, 8) reference; L9 (7.25, 9.7)-(7.25, 8.5) reference; L10 (7.25, 8.5)-(6.25, 8.5) reference; L11 (6.25, 8.5)-(6.25, 9.7) reference; L12 (6.25, 9.7)-(7.25, 9.7) reference; L13 (7.25, 11.4)-(7.25, 10.2) reference; L14 (7.25, 10.2)-(6.25, 10.2) reference; L15 (6.25, 10.2)-(6.25, 11.4) reference; L16 (6.25, 11.4)-(7.25, 11.4) reference; L17 (13.75, 6.3)-(13.75, 5.1) reference; L18 (13.75, 5.1)-(12.75, 5.1) reference; L19 (12.75, 5.1)-(12.75, 6.3) reference; L20 (12.75, 6.3)-(13.75, 6.3) reference; L21 (12.25, 9.7)-(12.25, 8.5) reference; L22 (12.25, 8.5)-(11.25, 8.5) reference; L23 (11.25, 8.5)-(11.25, 9.7) reference; L24 (11.25, 9.7)-(12.25, 9.7) reference; L25 (13.75, 11.4)-(13.75, 10.2) reference; L26 (13.75, 10.2)-(12.75, 10.2) reference; L27 (12.75, 10.2)-(12.75, 11.4) reference; L28 (12.75, 11.4)-(13.75, 11.4) reference; L29 (20.25, 6.3)-(20.25, 5.1) reference; L30 (20.25, 5.1)-(19.25, 5.1) reference; L31 (19.25, 5.1)-(19.25, 6.3) reference; L32 (19.25, 6.3)-(20.25, 6.3) reference; L33 (20.25, 8)-(20.25, 6.8) reference; L34 (20.25, 6.8)-(19.25, 6.8) reference; L35 (19.25, 6.8)-(19.25, 8) reference; L36 (19.25, 8)-(20.25, 8) reference; L37 (20.25, 9.7)-(20.25, 8.5) reference; L38 (20.25, 8.5)-(19.25, 8.5) reference; L39 (19.25, 8.5)-(19.25, 9.7) reference; L40 (19.25, 9.7)-(20.25, 9.7) reference; L41 (19.25, 10.2)-(19.25, 11.4) reference; L42 (19.25, 11.4)-(20.25, 11.4) reference; L43 (20.25, 11.4)-(20.25, 10.2) reference; L44 (20.25, 10.2)-(19.25, 10.2) reference; L45 (13.717, 9.7)-(13.717, 8.5) reference; L46 (13.717, 8.5)-(12.75, 8.5) reference; L47 (12.75, 8.5)-(12.75, 9.7) reference; L48 (12.75, 9.7)-(13.717, 9.7) reference; L49 (13.717, 8)-(13.717, 6.8) reference; L50 (13.717, 6.8)-(12.75, 6.8) reference; L51 (12.75, 6.8)-(12.75, 8) reference; L52 (12.75, 8)-(13.717, 8) reference; L53 (18.75, 11.4)-(18.75, 10.2) reference; L54 (18.75, 10.2)-(17.75, 10.2) reference; L55 (17.75, 10.2)-(17.75, 11.4) reference; L56 (17.75, 11.4)-(18.75, 11.4) reference; L57 (18.75, 9.7)-(18.75, 8.5) reference; L58 (18.75, 8.5)-(17.75, 8.5) reference; L59 (17.75, 8.5)-(17.75, 9.7) reference; L60 (17.75, 9.7)-(18.75, 9.7) reference; L61 (18.75, 8)-(18.75, 6.8) reference; L62 (18.75, 6.8)-(17.75, 6.8) reference; L63 (17.75, 6.8)-(17.75, 8) reference; L64 (17.75, 8)-(18.75, 8) reference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; 2 further points
  constraints: 24 end point, 6 parallel, 3 horizontal, 3 perpendicular
  dimensions: "d1663" = 4 distance between parallel lines of L108 L110; "d1664" = 4 distance of L98.start L98.end; "d1665" = 4 distance of L102.start L102.end; "d1666" = 4 distance of L106.start L106.end; "d1667" = 7.5 distance of L106.end L107.end; "d1668" = 3.5 distance between parallel lines of L97 L107; "d1669" = 2.5 distance between parallel lines of L103 L109; "d1670" = 2.5 distance between parallel lines of L99 L105; "d1671" = 0 distance between parallel lines of L106 L102; "d1672" = 0 distance between parallel lines of L104 L100; "d1673" = 0 distance between parallel lines of L111 L104
extrude "押し出し117" cut sketch "スケッチ124" distance "d1674" = 0.5; taper "d1675" = 0 deg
